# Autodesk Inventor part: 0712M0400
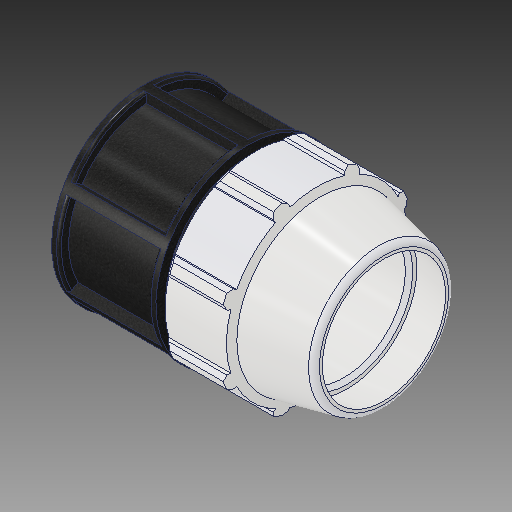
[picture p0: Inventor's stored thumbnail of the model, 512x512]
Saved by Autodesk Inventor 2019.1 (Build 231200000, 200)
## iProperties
Created: 2017-02
Part Number: 0712M0400
Material: PVC-Piping
Description: PLASSON END PLUG 4''
Document SubType Name: Modeling
Designer: KIM
Mass: 92.6774 g
Surface Area: 199.44 cm^2
Volume: 66.1981 cm^3
Density: 1.4 g/cm^3
Appearance: PTFE
Author: Кирилл
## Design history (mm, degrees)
derived "0712M0.ipt"
feature "Solid1::0712M0.ipt"
tag "TaggingFeature1"
body "Solid1"
other parameters: "d2" = 114.1, "d4" = 33.85457, "d5" = 59.2455, "d7" = 181.102, "d8" = 153.9367, "d9" = 33.85457, "d11" = 6.77091, "d12" = 153.9367, "d13" = 120 deg, "d15" = 12 deg, "d16" = 172.0469, "d18" = 5.705, "d19" = 35 deg, "d20" = 17.5 deg, "d21" = 168.42486, "d23" = 0, "d25" = 360 deg, "d27" = 3.62204, "d34" = 9.0551, "d36" = 0, "d42" = 59.2455, "d43" = 5.43306, "d46" = 3.423, "d53" = 2.282, "d55" = 360 deg, "d59" = 82.9437, "d64" = 236.982, "d66" = 18.1102, "d67" = 9.0551, "d68" = 214.884, "d70" = 153.9367, "d_" = 114.1, "E_" = 181.102, "H_" = 236.982, "l_" = 214.884
